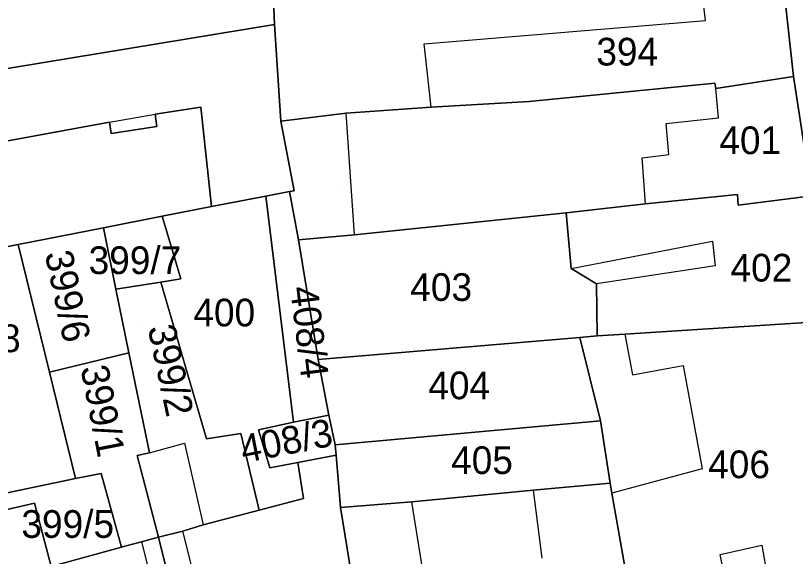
# Model space of a CAD drawing. Extents: x -263423 to -261326, y -1240067 to -1237864.
# Drawn here: x -263147.7 to -263091.4, y -1239663.3 to -1239624.2 of the extents above; entities that cross this region are included whole.
import ezdxf

# ---------------------------------------------------------------- set-up
doc = ezdxf.new("R2010")
doc.units = 0
for name, color, linetype in [('body_kn', 7, 'Continuous'), ('kladpar_druhypozemkov', 7, 'Continuous'), ('kladpar_hranice', 7, 'Continuous'), ('kladpar_parcelnecisla', 7, 'Continuous'), ('kladpar_plochy', 7, 'Continuous'), ('zappar_hrandruhpozemk', 7, 'Continuous')]:
    doc.layers.add(name, color=color, linetype=linetype)

msp = doc.modelspace()

# ---------------------------------------------------------------- linework, layer by layer
at = {"layer": 'body_kn'}
for p, q in [((-263129.03, -1239624.87), (-263129.03, -1239624.87)), ((-263129.03, -1239624.87), (-263129.03, -1239624.87)), ((-263097.92, -1239624.58), (-263097.92, -1239624.58)), ((-263118.22, -1239626.26), (-263118.22, -1239626.26)), ((-263091.56, -1239628.63), (-263091.56, -1239628.63)), ((-263097.24, -1239629.11), (-263097.24, -1239629.11)), ((-263097.17, -1239629.49), (-263097.17, -1239629.49)), ((-263110.64, -1239630.44), (-263110.64, -1239630.44)), ((-263110.64, -1239630.44), (-263110.64, -1239630.44)), ((-263134.35, -1239630.84), (-263134.35, -1239630.84)), ((-263117.73, -1239630.85), (-263117.73, -1239630.85)), ((-263117.73, -1239630.85), (-263117.73, -1239630.85)), ((-263137.65, -1239631.35), (-263137.65, -1239631.35)), ((-263123.85, -1239631.26), (-263123.85, -1239631.26)), ((-263096.99, -1239631.6), (-263096.99, -1239631.6)), ((-263140.95, -1239631.93), (-263140.95, -1239631.93)), ((-263140.95, -1239631.93), (-263140.95, -1239631.93)), ((-263128.58, -1239631.86), (-263128.58, -1239631.86)), ((-263100.76, -1239632.02), (-263100.76, -1239632.02)), ((-263140.82, -1239632.75), (-263140.82, -1239632.75)), ((-263137.53, -1239632.24), (-263137.53, -1239632.24)), ((-263100.57, -1239634.25), (-263100.57, -1239634.25)), ((-263102.49, -1239634.5), (-263102.49, -1239634.5)), ((-263129.65, -1239637.26), (-263129.65, -1239637.26)), ((-263129.65, -1239637.26), (-263129.65, -1239637.26)), ((-263127.94, -1239636.94), (-263127.94, -1239636.94)), ((-263127.62, -1239636.88), (-263127.62, -1239636.88)), ((-263095.61, -1239637.15), (-263095.61, -1239637.15)), ((-263095.61, -1239637.15), (-263095.61, -1239637.15)), ((-263102.25, -1239637.81), (-263102.25, -1239637.81)), ((-263102.25, -1239637.81), (-263102.25, -1239637.81)), ((-263133.58, -1239638.02), (-263133.58, -1239638.02)), ((-263095.55, -1239637.91), (-263095.55, -1239637.91)), ((-263137.14, -1239638.72), (-263137.14, -1239638.72)), ((-263107.99, -1239638.48), (-263107.99, -1239638.48)), ((-263107.99, -1239638.48), (-263107.99, -1239638.48)), ((-263141.39, -1239639.55), (-263141.39, -1239639.55)), ((-263141.39, -1239639.55), (-263141.39, -1239639.55)), ((-263123.25, -1239640.06), (-263123.25, -1239640.06)), ((-263123.25, -1239640.06), (-263123.25, -1239640.06)), ((-263127.3, -1239640.43), (-263127.3, -1239640.43)), ((-263097.41, -1239640.52), (-263097.41, -1239640.52)), ((-263147.54, -1239640.76), (-263147.54, -1239640.76)), ((-263147.54, -1239640.76), (-263147.54, -1239640.76)), ((-263097.22, -1239642.3), (-263097.22, -1239642.3)), ((-263107.62, -1239642.5), (-263107.62, -1239642.5)), ((-263107.62, -1239642.5), (-263107.62, -1239642.5)), ((-263137.25, -1239643.47), (-263137.25, -1239643.47)), ((-263135.8, -1239643.23), (-263135.8, -1239643.23)), ((-263140.49, -1239643.99), (-263140.49, -1239643.99)), ((-263105.78, -1239643.59), (-263105.78, -1239643.59)), ((-263105.73, -1239647.36), (-263105.73, -1239647.36)), ((-263103.75, -1239647.24), (-263103.75, -1239647.24)), ((-263103.75, -1239647.24), (-263103.75, -1239647.24)), ((-263107, -1239647.48), (-263107, -1239647.48)), ((-263107, -1239647.48), (-263107, -1239647.48)), ((-263139.55, -1239648.57), (-263139.55, -1239648.57)), ((-263125.89, -1239649.07), (-263125.89, -1239649.07)), ((-263125.89, -1239649.07), (-263125.89, -1239649.07)), ((-263099.54, -1239649.49), (-263099.54, -1239649.49)), ((-263145.28, -1239649.97), (-263145.28, -1239649.97)), ((-263145.28, -1239649.97), (-263145.28, -1239649.97)), ((-263103.18, -1239650.17), (-263103.18, -1239650.17)), ((-263127.66, -1239653.58), (-263127.66, -1239653.58)), ((-263125.12, -1239653.07), (-263125.12, -1239653.07)), ((-263125.12, -1239653.07), (-263125.12, -1239653.07)), ((-263105.49, -1239653.48), (-263105.49, -1239653.48)), ((-263105.49, -1239653.48), (-263105.49, -1239653.48)), ((-263130.2, -1239654.15), (-263130.2, -1239654.15)), ((-263131.47, -1239654.41), (-263131.47, -1239654.41)), ((-263135.53, -1239655.11), (-263135.53, -1239655.11)), ((-263133.94, -1239654.79), (-263133.94, -1239654.79)), ((-263133.94, -1239654.79), (-263133.94, -1239654.79)), ((-263124.65, -1239655.22), (-263124.65, -1239655.22)), ((-263138.06, -1239655.81), (-263138.06, -1239655.81)), ((-263138.06, -1239655.81), (-263138.06, -1239655.81)), ((-263138.95, -1239656), (-263138.95, -1239656)), ((-263124.59, -1239655.97), (-263124.59, -1239655.97)), ((-263129.37, -1239656.88), (-263129.37, -1239656.88)), ((-263127.34, -1239656.5), (-263127.34, -1239656.5)), ((-263098.17, -1239656.96), (-263098.17, -1239656.96)), ((-263141.55, -1239657.29), (-263141.55, -1239657.29)), ((-263141.55, -1239657.29), (-263141.55, -1239657.29)), ((-263143.39, -1239657.65), (-263143.39, -1239657.65)), ((-263104.81, -1239658), (-263104.81, -1239658)), ((-263104.81, -1239658), (-263104.81, -1239658)), ((-263110.36, -1239658.49), (-263110.36, -1239658.49)), ((-263110.36, -1239658.49), (-263110.36, -1239658.49)), ((-263126.95, -1239659.1), (-263126.95, -1239659.1)), ((-263104.68, -1239658.71), (-263104.68, -1239658.71)), ((-263146.37, -1239659.43), (-263146.37, -1239659.43)), ((-263124.28, -1239659.75), (-263124.28, -1239659.75)), ((-263119.11, -1239659.33), (-263119.11, -1239659.33)), ((-263130.13, -1239659.93), (-263130.13, -1239659.93)), ((-263130.13, -1239659.93), (-263130.13, -1239659.93)), ((-263135.64, -1239661.46), (-263135.64, -1239661.46)), ((-263134.19, -1239661.01), (-263134.19, -1239661.01)), ((-263137.42, -1239661.9), (-263137.42, -1239661.9)), ((-263137.42, -1239661.9), (-263137.42, -1239661.9)), ((-263140.09, -1239662.61), (-263140.09, -1239662.61)), ((-263139.83, -1239662.54), (-263139.83, -1239662.54)), ((-263138.63, -1239662.22), (-263138.63, -1239662.22)), ((-263138.63, -1239662.22), (-263138.63, -1239662.22)), ((-263093.85, -1239662.46), (-263093.85, -1239662.46)), ((-263096.85, -1239663.15), (-263096.85, -1239663.15)), ((-263096.85, -1239663.15), (-263096.85, -1239663.15))]:
    msp.add_line(p, q, dxfattribs=at)
at = {"layer": 'kladpar_druhypozemkov'}
for p, q in [((-263103.8, -1239625.73), (-263103.8, -1239625.73)), ((-263095.2, -1239632.23), (-263095.2, -1239632.23)), ((-263124.49, -1239636.62), (-263124.49, -1239636.62)), ((-263094, -1239640.93), (-263094, -1239640.93)), ((-263138.74, -1239641.45), (-263138.74, -1239641.45)), ((-263117, -1239642.43), (-263117, -1239642.43)), ((-263128.3, -1239643.53), (-263128.3, -1239643.53)), ((-263142.76, -1239645.04), (-263142.76, -1239645.04)), ((-263132.7, -1239644.73), (-263132.7, -1239644.73)), ((-263138.58, -1239646.5), (-263138.58, -1239646.5)), ((-263116, -1239650.33), (-263116, -1239650.33)), ((-263140.26, -1239652.75), (-263140.26, -1239652.75)), ((-263127.2, -1239654.03), (-263127.2, -1239654.03)), ((-263095.8, -1239655.23), (-263095.8, -1239655.23)), ((-263114.3, -1239655.73), (-263114.3, -1239655.73)), ((-263143.31, -1239660.39), (-263143.31, -1239660.39))]:
    msp.add_line(p, q, dxfattribs=at)
at = {"layer": 'kladpar_hranice'}
for points in [[(-263083.66, -1239666.98), (-263087.57, -1239654.65), (-263089.13, -1239646.3), (-263090.25, -1239637.24), (-263091.56, -1239628.63), (-263092.48, -1239620.27), (-263092.6, -1239618.68), (-263093.34, -1239611.67), (-263093.46, -1239608.22), (-263093.52, -1239607.08), (-263093.76, -1239602.68), (-263093.94, -1239598.98), (-263093.99, -1239597.51), (-263094.33, -1239584.51), (-263094.43, -1239577.42), (-263094.27, -1239577.42), (-263094.22, -1239572.27)], [(-263166, -1239602.54), (-263161.05, -1239601.9), (-263147.91, -1239600.37), (-263143.15, -1239599.8), (-263138.2, -1239599.22), (-263130.91, -1239598.65), (-263130.46, -1239604.93), (-263129.68, -1239614.9), (-263129.1, -1239623.16), (-263129.03, -1239624.87), (-263181.63, -1239633.53), (-263182.92, -1239618.55), (-263183.3, -1239615.82), (-263184.65, -1239604.83), (-263166, -1239602.54)], [(-263102.12, -1239621.12), (-263099.18, -1239620.81), (-263092.48, -1239620.27), (-263091.56, -1239628.63), (-263097.17, -1239629.49), (-263097.24, -1239629.11), (-263110.64, -1239630.44), (-263117.73, -1239630.85), (-263123.85, -1239631.26), (-263128.58, -1239631.86), (-263129.03, -1239624.87), (-263129.1, -1239623.16), (-263108.5, -1239621.59), (-263102.12, -1239621.12)], [(-263129.03, -1239624.87), (-263128.58, -1239631.86), (-263127.62, -1239636.88), (-263127.94, -1239636.94), (-263129.65, -1239637.26), (-263133.58, -1239638.02), (-263134.35, -1239630.84), (-263137.65, -1239631.35), (-263137.53, -1239632.24), (-263140.82, -1239632.75), (-263140.95, -1239631.93), (-263152.5, -1239634.03), (-263167.22, -1239636.83), (-263168.8, -1239638.67), (-263168.35, -1239642.74), (-263168.16, -1239645.47), (-263179.9, -1239648.27), (-263180.28, -1239644.77), (-263181.63, -1239633.53), (-263129.03, -1239624.87)], [(-263110.64, -1239630.44), (-263097.24, -1239629.11), (-263097.17, -1239629.49), (-263091.56, -1239628.63), (-263090.25, -1239637.24), (-263095.55, -1239637.91), (-263095.61, -1239637.15), (-263102.25, -1239637.81), (-263107.99, -1239638.48), (-263123.25, -1239640.06), (-263127.3, -1239640.43), (-263127.94, -1239636.94), (-263127.62, -1239636.88), (-263128.58, -1239631.86), (-263123.85, -1239631.26), (-263117.73, -1239630.85), (-263110.64, -1239630.44)], [(-263152.5, -1239634.03), (-263140.95, -1239631.93), (-263140.82, -1239632.75), (-263137.53, -1239632.24), (-263137.65, -1239631.35), (-263134.35, -1239630.84), (-263133.58, -1239638.02), (-263137.14, -1239638.72), (-263141.39, -1239639.55), (-263147.54, -1239640.76), (-263154.01, -1239642.03), (-263167.34, -1239645.28), (-263168.16, -1239645.47), (-263168.35, -1239642.74), (-263168.8, -1239638.67), (-263167.22, -1239636.83), (-263152.5, -1239634.03)], [(-263129.65, -1239637.26), (-263127.66, -1239653.58), (-263130.2, -1239654.15), (-263129.37, -1239656.88), (-263127.34, -1239656.5), (-263126.95, -1239659.1), (-263130.13, -1239659.93), (-263131.47, -1239654.41), (-263133.94, -1239654.79), (-263137.25, -1239643.47), (-263135.8, -1239643.23), (-263137.14, -1239638.72), (-263133.58, -1239638.02), (-263129.65, -1239637.26)], [(-263125.89, -1239649.07), (-263125.12, -1239653.07), (-263127.66, -1239653.58), (-263129.65, -1239637.26), (-263127.94, -1239636.94), (-263127.3, -1239640.43), (-263125.89, -1239649.07)], [(-263095.61, -1239637.15), (-263095.55, -1239637.91), (-263090.25, -1239637.24), (-263089.13, -1239646.3), (-263103.75, -1239647.24), (-263105.73, -1239647.36), (-263105.78, -1239643.59), (-263107.62, -1239642.5), (-263107.99, -1239638.48), (-263102.25, -1239637.81), (-263095.61, -1239637.15)], [(-263141.39, -1239639.55), (-263137.14, -1239638.72), (-263135.8, -1239643.23), (-263137.25, -1239643.47), (-263140.49, -1239643.99), (-263141.39, -1239639.55)], [(-263107.99, -1239638.48), (-263107.62, -1239642.5), (-263105.78, -1239643.59), (-263105.73, -1239647.36), (-263107, -1239647.48), (-263125.89, -1239649.07), (-263127.3, -1239640.43), (-263123.25, -1239640.06), (-263107.99, -1239638.48)], [(-263141.39, -1239639.55), (-263140.49, -1239643.99), (-263139.55, -1239648.57), (-263145.28, -1239649.97), (-263147.54, -1239640.76), (-263141.39, -1239639.55)], [(-263147.54, -1239640.76), (-263145.28, -1239649.97), (-263143.39, -1239657.65), (-263149.86, -1239658.99), (-263151.27, -1239653.34), (-263154.01, -1239642.03), (-263147.54, -1239640.76)], [(-263133.94, -1239654.79), (-263131.47, -1239654.41), (-263130.13, -1239659.93), (-263134.19, -1239661.01), (-263135.64, -1239661.46), (-263137.42, -1239661.9), (-263138.95, -1239656), (-263138.06, -1239655.81), (-263139.55, -1239648.57), (-263140.49, -1239643.99), (-263137.25, -1239643.47), (-263133.94, -1239654.79)], [(-263089.13, -1239646.3), (-263087.57, -1239654.65), (-263083.66, -1239666.98), (-263102.19, -1239672.87), (-263104.68, -1239658.71), (-263104.81, -1239658), (-263105.49, -1239653.48), (-263107, -1239647.48), (-263105.73, -1239647.36), (-263103.75, -1239647.24), (-263089.13, -1239646.3)], [(-263107, -1239647.48), (-263105.49, -1239653.48), (-263124.65, -1239655.22), (-263125.12, -1239653.07), (-263125.89, -1239649.07), (-263107, -1239647.48)], [(-263145.28, -1239649.97), (-263139.55, -1239648.57), (-263138.06, -1239655.81), (-263138.95, -1239656), (-263137.42, -1239661.9), (-263138.63, -1239662.22), (-263139.83, -1239662.54), (-263140.09, -1239662.61), (-263141.55, -1239657.29), (-263143.39, -1239657.65), (-263145.28, -1239649.97)], [(-263125.12, -1239653.07), (-263124.65, -1239655.22), (-263124.59, -1239655.97), (-263127.34, -1239656.5), (-263129.37, -1239656.88), (-263130.2, -1239654.15), (-263127.66, -1239653.58), (-263125.12, -1239653.07)], [(-263105.49, -1239653.48), (-263104.81, -1239658), (-263110.36, -1239658.49), (-263119.11, -1239659.33), (-263124.28, -1239659.75), (-263124.59, -1239655.97), (-263124.65, -1239655.22), (-263105.49, -1239653.48)], [(-263130.13, -1239659.93), (-263126.95, -1239659.1), (-263127.34, -1239656.5), (-263124.59, -1239655.97), (-263124.28, -1239659.75), (-263122.85, -1239668.49), (-263121.91, -1239674.4), (-263122.51, -1239674.55), (-263122.36, -1239675.31), (-263121.8, -1239677.53), (-263121.67, -1239678.18), (-263130.92, -1239680.26), (-263132.76, -1239680.64), (-263133.61, -1239677.22), (-263137.42, -1239661.9), (-263135.64, -1239661.46), (-263134.19, -1239661.01), (-263130.13, -1239659.93)], [(-263141.55, -1239657.29), (-263140.09, -1239662.61), (-263145.16, -1239664), (-263146.37, -1239659.43), (-263149.61, -1239660.19), (-263149.86, -1239658.99), (-263143.39, -1239657.65), (-263141.55, -1239657.29)], [(-263104.81, -1239658), (-263104.68, -1239658.71), (-263102.19, -1239672.87), (-263110.23, -1239675.06), (-263113.17, -1239675.87), (-263121.67, -1239678.18), (-263121.8, -1239677.53), (-263122.36, -1239675.31), (-263122.51, -1239674.55), (-263121.91, -1239674.4), (-263122.85, -1239668.49), (-263124.28, -1239659.75), (-263119.11, -1239659.33), (-263110.36, -1239658.49), (-263104.81, -1239658)], [(-263137.42, -1239661.9), (-263133.61, -1239677.22), (-263134.86, -1239677.53), (-263144.82, -1239680.01), (-263149.61, -1239660.19), (-263146.37, -1239659.43), (-263145.16, -1239664), (-263140.09, -1239662.61), (-263139.83, -1239662.54), (-263138.63, -1239662.22), (-263137.42, -1239661.9)]]:
    msp.add_lwpolyline(points, dxfattribs=at)
at = {"layer": 'kladpar_plochy'}
msp.add_lwpolyline([(-263083.66, -1239666.98), (-263087.57, -1239654.65), (-263089.13, -1239646.3), (-263090.25, -1239637.24), (-263091.56, -1239628.63), (-263092.48, -1239620.27), (-263092.6, -1239618.68), (-263093.34, -1239611.67), (-263093.46, -1239608.22), (-263093.52, -1239607.08), (-263093.76, -1239602.68), (-263093.94, -1239598.98), (-263093.99, -1239597.51), (-263094.33, -1239584.51), (-263094.43, -1239577.42), (-263094.27, -1239577.42), (-263094.22, -1239572.27)], dxfattribs=at)
for points in [[(-263166, -1239602.54), (-263161.05, -1239601.9), (-263147.91, -1239600.37), (-263143.15, -1239599.8), (-263138.2, -1239599.22), (-263130.91, -1239598.65), (-263130.46, -1239604.93), (-263129.68, -1239614.9), (-263129.1, -1239623.16), (-263129.03, -1239624.87), (-263181.63, -1239633.53), (-263182.92, -1239618.55), (-263183.3, -1239615.82), (-263184.65, -1239604.83)], [(-263102.12, -1239621.12), (-263099.18, -1239620.81), (-263092.48, -1239620.27), (-263091.56, -1239628.63), (-263097.17, -1239629.49), (-263097.24, -1239629.11), (-263110.64, -1239630.44), (-263117.73, -1239630.85), (-263123.85, -1239631.26), (-263128.58, -1239631.86), (-263129.03, -1239624.87), (-263129.1, -1239623.16), (-263108.5, -1239621.59)], [(-263129.03, -1239624.87), (-263128.58, -1239631.86), (-263127.62, -1239636.88), (-263127.94, -1239636.94), (-263129.65, -1239637.26), (-263133.58, -1239638.02), (-263134.35, -1239630.84), (-263137.65, -1239631.35), (-263137.53, -1239632.24), (-263140.82, -1239632.75), (-263140.95, -1239631.93), (-263152.5, -1239634.03), (-263167.22, -1239636.83), (-263168.8, -1239638.67), (-263168.35, -1239642.74), (-263168.16, -1239645.47), (-263179.9, -1239648.27), (-263180.28, -1239644.77), (-263181.63, -1239633.53)], [(-263110.64, -1239630.44), (-263097.24, -1239629.11), (-263097.17, -1239629.49), (-263091.56, -1239628.63), (-263090.25, -1239637.24), (-263095.55, -1239637.91), (-263095.61, -1239637.15), (-263102.25, -1239637.81), (-263107.99, -1239638.48), (-263123.25, -1239640.06), (-263127.3, -1239640.43), (-263127.94, -1239636.94), (-263127.62, -1239636.88), (-263128.58, -1239631.86), (-263123.85, -1239631.26), (-263117.73, -1239630.85)], [(-263152.5, -1239634.03), (-263140.95, -1239631.93), (-263140.82, -1239632.75), (-263137.53, -1239632.24), (-263137.65, -1239631.35), (-263134.35, -1239630.84), (-263133.58, -1239638.02), (-263137.14, -1239638.72), (-263141.39, -1239639.55), (-263147.54, -1239640.76), (-263154.01, -1239642.03), (-263167.34, -1239645.28), (-263168.16, -1239645.47), (-263168.35, -1239642.74), (-263168.8, -1239638.67), (-263167.22, -1239636.83)], [(-263129.65, -1239637.26), (-263127.66, -1239653.58), (-263130.2, -1239654.15), (-263129.37, -1239656.88), (-263127.34, -1239656.5), (-263126.95, -1239659.1), (-263130.13, -1239659.93), (-263131.47, -1239654.41), (-263133.94, -1239654.79), (-263137.25, -1239643.47), (-263135.8, -1239643.23), (-263137.14, -1239638.72), (-263133.58, -1239638.02)], [(-263125.89, -1239649.07), (-263125.12, -1239653.07), (-263127.66, -1239653.58), (-263129.65, -1239637.26), (-263127.94, -1239636.94), (-263127.3, -1239640.43)], [(-263095.61, -1239637.15), (-263095.55, -1239637.91), (-263090.25, -1239637.24), (-263089.13, -1239646.3), (-263103.75, -1239647.24), (-263105.73, -1239647.36), (-263105.78, -1239643.59), (-263107.62, -1239642.5), (-263107.99, -1239638.48), (-263102.25, -1239637.81)], [(-263141.39, -1239639.55), (-263137.14, -1239638.72), (-263135.8, -1239643.23), (-263137.25, -1239643.47), (-263140.49, -1239643.99)], [(-263107.99, -1239638.48), (-263107.62, -1239642.5), (-263105.78, -1239643.59), (-263105.73, -1239647.36), (-263107, -1239647.48), (-263125.89, -1239649.07), (-263127.3, -1239640.43), (-263123.25, -1239640.06)], [(-263141.39, -1239639.55), (-263140.49, -1239643.99), (-263139.55, -1239648.57), (-263145.28, -1239649.97), (-263147.54, -1239640.76)], [(-263147.54, -1239640.76), (-263145.28, -1239649.97), (-263143.39, -1239657.65), (-263149.86, -1239658.99), (-263151.27, -1239653.34), (-263154.01, -1239642.03)], [(-263133.94, -1239654.79), (-263131.47, -1239654.41), (-263130.13, -1239659.93), (-263134.19, -1239661.01), (-263135.64, -1239661.46), (-263137.42, -1239661.9), (-263138.95, -1239656), (-263138.06, -1239655.81), (-263139.55, -1239648.57), (-263140.49, -1239643.99), (-263137.25, -1239643.47)], [(-263089.13, -1239646.3), (-263087.57, -1239654.65), (-263083.66, -1239666.98), (-263102.19, -1239672.87), (-263104.68, -1239658.71), (-263104.81, -1239658), (-263105.49, -1239653.48), (-263107, -1239647.48), (-263105.73, -1239647.36), (-263103.75, -1239647.24)], [(-263107, -1239647.48), (-263105.49, -1239653.48), (-263124.65, -1239655.22), (-263125.12, -1239653.07), (-263125.89, -1239649.07)], [(-263145.28, -1239649.97), (-263139.55, -1239648.57), (-263138.06, -1239655.81), (-263138.95, -1239656), (-263137.42, -1239661.9), (-263138.63, -1239662.22), (-263139.83, -1239662.54), (-263140.09, -1239662.61), (-263141.55, -1239657.29), (-263143.39, -1239657.65)], [(-263125.12, -1239653.07), (-263124.65, -1239655.22), (-263124.59, -1239655.97), (-263127.34, -1239656.5), (-263129.37, -1239656.88), (-263130.2, -1239654.15), (-263127.66, -1239653.58)], [(-263105.49, -1239653.48), (-263104.81, -1239658), (-263110.36, -1239658.49), (-263119.11, -1239659.33), (-263124.28, -1239659.75), (-263124.59, -1239655.97), (-263124.65, -1239655.22)], [(-263130.13, -1239659.93), (-263126.95, -1239659.1), (-263127.34, -1239656.5), (-263124.59, -1239655.97), (-263124.28, -1239659.75), (-263122.85, -1239668.49), (-263121.91, -1239674.4), (-263122.51, -1239674.55), (-263122.36, -1239675.31), (-263121.8, -1239677.53), (-263121.67, -1239678.18), (-263130.92, -1239680.26), (-263132.76, -1239680.64), (-263133.61, -1239677.22), (-263137.42, -1239661.9), (-263135.64, -1239661.46), (-263134.19, -1239661.01)], [(-263141.55, -1239657.29), (-263140.09, -1239662.61), (-263145.16, -1239664), (-263146.37, -1239659.43), (-263149.61, -1239660.19), (-263149.86, -1239658.99), (-263143.39, -1239657.65)], [(-263104.81, -1239658), (-263104.68, -1239658.71), (-263102.19, -1239672.87), (-263110.23, -1239675.06), (-263113.17, -1239675.87), (-263121.67, -1239678.18), (-263121.8, -1239677.53), (-263122.36, -1239675.31), (-263122.51, -1239674.55), (-263121.91, -1239674.4), (-263122.85, -1239668.49), (-263124.28, -1239659.75), (-263119.11, -1239659.33), (-263110.36, -1239658.49)], [(-263137.42, -1239661.9), (-263133.61, -1239677.22), (-263134.86, -1239677.53), (-263144.82, -1239680.01), (-263149.61, -1239660.19), (-263146.37, -1239659.43), (-263145.16, -1239664), (-263140.09, -1239662.61), (-263139.83, -1239662.54), (-263138.63, -1239662.22)]]:
    msp.add_lwpolyline(points, close=True, dxfattribs=at)
at = {"layer": 'zappar_hrandruhpozemk'}
for p, q in [((-263118.22, -1239626.26), (-263097.92, -1239624.58)), ((-263117.73, -1239630.85), (-263118.22, -1239626.26)), ((-263140.95, -1239631.93), (-263137.65, -1239631.35)), ((-263123.25, -1239640.06), (-263123.85, -1239631.26)), ((-263100.57, -1239634.25), (-263100.76, -1239632.02)), ((-263107.62, -1239642.5), (-263097.41, -1239640.52)), ((-263097.41, -1239640.52), (-263097.22, -1239642.3)), ((-263097.22, -1239642.3), (-263105.78, -1239643.59)), ((-263099.54, -1239649.49), (-263098.17, -1239656.96)), ((-263138.06, -1239655.81), (-263135.53, -1239655.11)), ((-263135.53, -1239655.11), (-263134.19, -1239661.01)), ((-263098.17, -1239656.96), (-263104.68, -1239658.71)), ((-263110.36, -1239658.49), (-263109.74, -1239663.4)), ((-263131.88, -1239676.7), (-263135.64, -1239661.46)), ((-263138.63, -1239662.22), (-263134.86, -1239677.53)), ((-263096.85, -1239663.15), (-263093.85, -1239662.46))]:
    msp.add_line(p, q, dxfattribs=at)
for points in [[(-263097.92, -1239624.58), (-263098.11, -1239622.92), (-263101.87, -1239623.16), (-263102.12, -1239621.12)], [(-263100.76, -1239632.02), (-263096.99, -1239631.6), (-263097.17, -1239629.49)], [(-263102.25, -1239637.81), (-263102.49, -1239634.5), (-263100.57, -1239634.25)], [(-263103.75, -1239647.24), (-263103.18, -1239650.17), (-263099.54, -1239649.49)], [(-263113.13, -1239664.27), (-263116, -1239665.08), (-263118.11, -1239665.65), (-263119.11, -1239659.33)], [(-263093.85, -1239662.46), (-263093.41, -1239664.95), (-263096.35, -1239665.63), (-263096.85, -1239663.15)]]:
    msp.add_lwpolyline(points, dxfattribs=at)

# ---------------------------------------------------------------- texts
at = {"layer": 'kladpar_parcelnecisla'}
for s, p in [('394', (-263105.801, -1239627.83)), ('401', (-263096.921, -1239634.23)), ('399/7', (-263142.454, -1239642.89)), ('402', (-263096.117, -1239643.43)), ('403', (-263119.233, -1239644.83)), ('400', (-263134.892, -1239646.67)), ('398', (-263151.825, -1239648.53)), ('404', (-263117.93, -1239651.93)), ('405', (-263116.286, -1239657.33)), ('406', (-263097.73, -1239657.63)), ('399/5', (-263147.307, -1239661.94))]:
    msp.add_text(s, height=2, dxfattribs=at).set_placement(p)
for s, rotation, p in [('399/6', 282, (-263145.629, -1239641.407)), ('408/4', 277, (-263127.912, -1239643.871)), ('399/2', 282, (-263138.197, -1239646.762)), ('399/1', 281, (-263143.044, -1239649.657)), ('408/3', 11, (-263131.276, -1239656.544))]:
    msp.add_text(s, height=2, rotation=rotation, dxfattribs=at).set_placement(p)

doc.saveas('drawing.dxf')
